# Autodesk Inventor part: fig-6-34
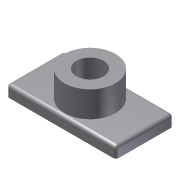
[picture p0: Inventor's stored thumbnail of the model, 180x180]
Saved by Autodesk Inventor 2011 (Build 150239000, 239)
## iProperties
Created: 2004-05
Part Number: fig-6-34
Document SubType Name: Modeling
Designer: CADCIM Technologies
Manufacturer: Standard
Standards Organization: Custom
Density: 1 g/cm^3
Author: CADCIM Technologies
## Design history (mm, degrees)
sketch "Sketch1"
  geometry: L1 (-39.276, -18.692)-(33.721, -18.692); L2 (33.721, -18.692)-(33.721, 19.728); L3 (33.721, 19.728)-(-39.276, 19.728); L4 (-39.276, 19.728)-(-39.276, -18.692)
  constraints: 8 end point, 2 parallel, 1 horizontal, 1 perpendicular
extrude "Extrusion1" new body sketch "Sketch1" distance "d0" = 7.5; taper "d1" = 0 deg
sketch "Sketch2"
  geometry: C1 r 17 at (-2.778, 0.518)
  constraints: 1 centre point
  dimensions: "d16" = 34 diameter of C1
extrude "Extrusion2" join sketch "Sketch2" distance "d3" = 17.25; taper "d4" = 0 deg
hole "Hole1" diameter "d8" = 18; stored, may be unused: countersink angle "d12" = 90 deg, drill point angle "d14" = 118 deg; dims "d6" = 10, "d7" = 10, "d9" = 6, "d10" = 4, "d11" = 2, "d13" = 8
fillet "Fillet4" dims "d17" = 2
body "Solid1"
